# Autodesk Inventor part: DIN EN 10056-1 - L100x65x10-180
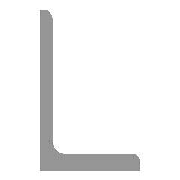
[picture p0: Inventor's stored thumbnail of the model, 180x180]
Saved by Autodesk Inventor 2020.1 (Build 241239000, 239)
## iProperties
Created: 2019-01
Part Number: DIN EN 10056-1 - L100x65x10-180
Material: Stahl, weich
Description: Warmgewalztes Baustahlprofil - ungleichschenklig
Document SubType Name: Modeling
Standard: DIN
Designer: lutzd
Standard Revision: 1998
Standards Organization: DIN
Language: de-DE
Size Designation: L100x65x10
Categories: <MemberInstance><Categories><Category DisplayName="Profile" InternalName="089c4875-fa83-4c05-b084-43b9cc11f5ed" Mnemonic="GRDR"><CategoryParameter DisplayName="
Stock Number: L100x65x10
Mass: 2144.23 g
Surface Area: 618.766 cm^2
Volume: 273.15 cm^3
Density: 7.85 g/cm^3
Appearance: Halbpoliert
_CCFamilyMember: 210
_CCFamilyDisplayName: DIN EN 10056-1 (L-Profil) - Warmgewalztes Baustahlprofil - ungleichschenklig
_FrameMemberDoc: Frame Member File
_Version: 15.0.0
_GetPNFromCC: 1
G_L: 180,000 mm
G_W: 65,000 mm
G_H: 100,000 mm
DocNumber: ADSK-014179
Folder: .
Dimensions: 65x100x180 mm
Mass: 2,144 kg
IsCustomPart: 1
Title: Profil-Bauteil
Author: lutzd
Revision Number: -
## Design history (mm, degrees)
node "Startebene"
node "Endebene"
sketch "Skizze"
  geometry: L1 (-6.3, 61.4)-(-6.3, -13.6); L2 (-16.3, 66.4)-(-11.3, 66.4); L3 (-16.3, -33.6)-(-16.3, 66.4); L4 (48.7, -33.6)-(-16.3, -33.6); L5 (48.7, -28.6)-(48.7, -33.6); L6 (3.7, -23.6)-(43.7, -23.6); L7 (0, 87.643)-(0, -53.807) reference; L8 (-29.507, 0)-(62.943, 0) reference; A1 r 10 centre (3.7, -13.6) between (-6.3, -13.6) and (3.7, -23.6); A2 r 5 centre (-11.3, 61.4) between (-6.3, 61.4) and (-11.3, 66.4); A3 r 5 centre (43.7, -28.6) between (48.7, -28.6) and (43.7, -23.6); 3 further points
  constraints: 12 end point, 6 point on circle, 6 point on line, 6 tangent, 3 centre point, 3 horizontal, 3 vertical, 1 equal radius
  dimensions: "d4" = 65 distance of L4.start L3.start (= b); "d6" = 100 distance of L3.start L2.start (= ParH); "d8" = 10 distance of point (48.7, -23.6) L4.start (= ParT); "d10" = 10 distance of L2.start point (-6.3, 66.4) (= ParT); "d17" = 10 radius of A1 (= R); "d18" = 5 radius of A2 (= R1); "d19" = 33.6 distance between parallel lines of L8 L4 (= ex); "d20" = 16.3 distance between parallel lines of L3 L7 (= ey)
extrude "Körper" new body sketch "Skizze" stored distance "d11" = 180 (= G_L); taper "d12" = 0 deg
node "Driven Length"
  sketch "Sketch3"
    geometry: L1 (0, 0)-(10, 0) reference
    constraints: 2 end point, 1 horizontal
  workplane "Work Plane10"
  sketch "Sketch4"
    geometry: L1 (-2, 0)-(12, 0) reference; L2 (-2, 180)-(12, 180) reference
    dimensions: "d24" = 180 distance between parallel lines of L1 L2 (derived)
sketch "Skizze5"
  geometry: L1 (154, 0)-(154, 18); L2 (158, 0)-(158, 18); L3 (150, 18)-(150, 0); L4 (22, 64)-(22, 46); L5 (26, 46)-(26, 64); L6 (30, 46)-(30, 64); L7 (150, 64)-(150, 46); L8 (154, 46)-(154, 64); L9 (158, 46)-(158, 64); L10 (22, 18)-(22, 0); L11 (26, 0)-(26, 18); L12 (30, 0)-(30, 18); L13 (154, 9)-(26, 9); L14 (26, 9)-(26, 55); L15 (26, 55)-(154, 55); L16 (154, 55)-(154, 9); L17 (180, 80)-(0, 80) reference; A1 r 4 centre (154, 0) between (150, 0) and (158, 0); A2 r 4 centre (154, 18) between (158, 18) and (150, 18); A3 r 4 centre (26, 64) between (30, 64) and (22, 64); A4 r 4 centre (26, 46) between (22, 46) and (30, 46); A5 r 4 centre (154, 64) between (158, 64) and (150, 64); A6 r 4 centre (154, 46) between (150, 46) and (158, 46); A7 r 4 centre (26, 18) between (30, 18) and (22, 18); A8 r 4 centre (26, 0) between (22, 0) and (30, 0); 10 further points
  constraints: 40 end point, 16 point on circle, 16 tangent, 8 centre point, 6 midpoint, 6 parallel, 4 coincident, 4 vertical, 1 horizontal, 1 perpendicular, 1 vertical alignment
  dimensions: "d35" = 18 distance of L1.start L1.end (= d37); "d36" = 8 diameter of A2; "d37" = 18 distance of L5.start L5.end; "d38" = 8 diameter of A3; "d39" = 18 distance of L8.start L8.end (= d37); "d40" = 8 diameter of A5; "d41" = 18 distance of L11.start L11.end; "d42" = 8 diameter of A7; "d43" = 128 distance of L14.end L15.end; "d44" = 46 distance of L13.end L14.end; "d46" = 16 distance from line of L17 L5.end
extrude "Extrusion2" cut sketch "Skizze5" extent not by distance; stored distance "d47" = 55; taper "d48" = 0 deg
workpoint "Arbeitspunkt2"
workpoint "Arbeitspunkt3"
workpoint "Arbeitspunkt4"
workpoint "Arbeitspunkt5"
workaxis "Arbeitsachse1"
workaxis "Arbeitsachse2"
workaxis "Arbeitsachse3"
workaxis "Arbeitsachse4"
body "Solid1"
other parameters: "b" = 65 [user parameter; used in 1 equation term], "ParT" = 10 [user parameter; used in 2 equation terms], "R1" = 5 [user parameter; used in 1 equation term], "G_L" = 180 (= d24) [user parameter; used in 1 equation term], "ParH" = 100 [user parameter; used in 1 equation term], "R" = 10 [user parameter; used in 1 equation term], "d7" = 4 (derived), "d9" = 4 (derived), "ey" = 16.3 [user parameter; used in 1 equation term], "ex" = 33.6 [user parameter; used in 1 equation term], "G_OFFSET_START" = 0 [user parameter; used in 1 equation term], "G_OFFSET_END" = 0 [user parameter; used in 1 equation term], "d21" = 0 (computed from G_OFFSET_START), "d23" = 90 deg
